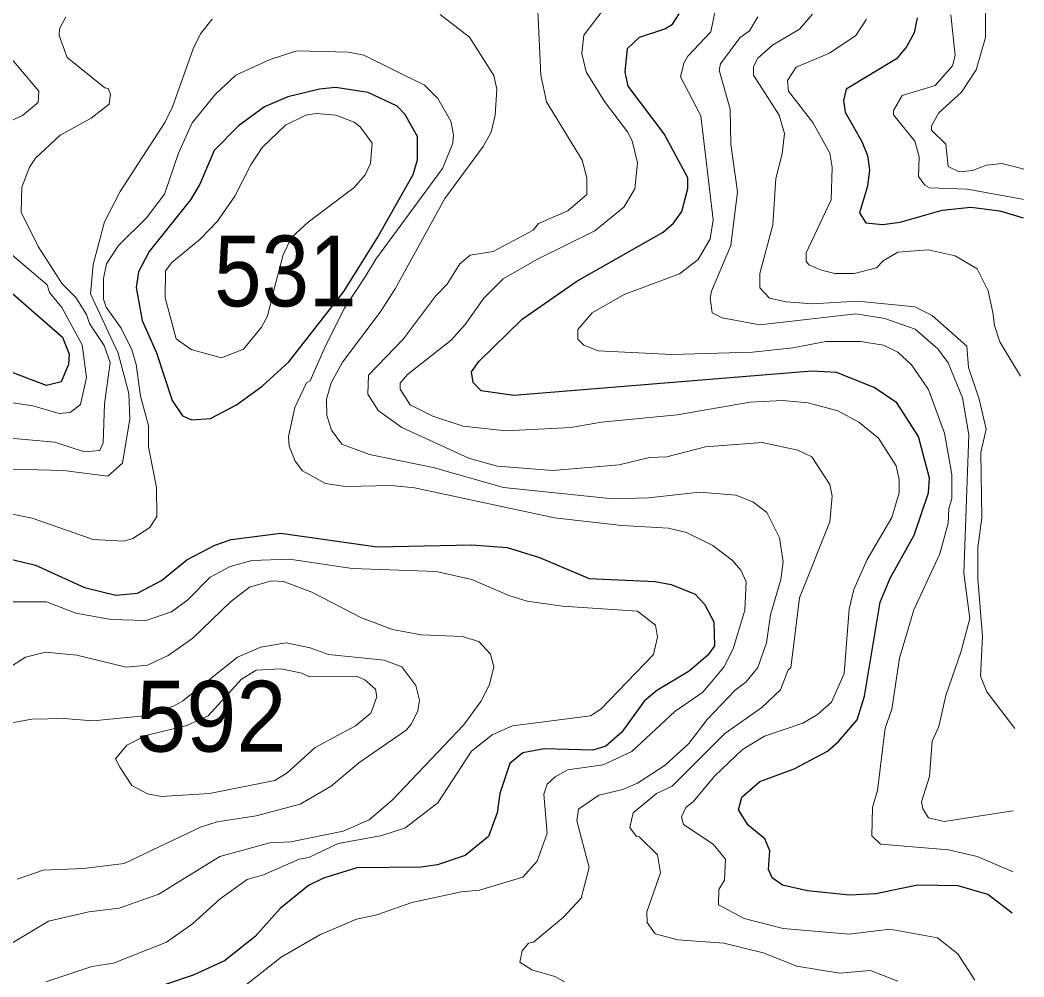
# Model space of a CAD drawing. Extents: x 673.3 to 698.5, y 6984.3 to 7012.3.
# Drawn here: x 696.93 to 698.064, y 6986.015 to 6987.096 of the extents above; entities that cross this region are included whole.
import ezdxf

# ---------------------------------------------------------------- set-up
doc = ezdxf.new("R2010")
doc.units = 0
doc.header["$LTSCALE"] = 0.032
doc.layers.add('1', color=7, linetype='Continuous', lineweight=25)
doc.layers.add('2', color=7, linetype='Continuous', lineweight=13)
doc.layers.add('21', color=7, linetype='Continuous')

msp = doc.modelspace()

# ---------------------------------------------------------------- linework, layer by layer
at = {"layer": '1'}
for points in [[(698.0509, 6986.0873), (698.0235, 6986.1082), (697.9901, 6986.118), (697.9442, 6986.1188), (697.897, 6986.109), (697.8672, 6986.1075), (697.82, 6986.1123), (697.7917, 6986.1188), (697.78, 6986.127), (697.7758, 6986.1366), (697.7775, 6986.1576), (697.7717, 6986.1711), (697.753, 6986.1866), (697.7418, 6986.2038), (697.7458, 6986.2181), (697.7662, 6986.2357), (697.8047, 6986.2501), (697.8425, 6986.2701), (697.855, 6986.2809), (697.876, 6986.3054), (697.8843, 6986.3324), (697.9018, 6986.4384), (697.9134, 6986.4655), (697.9404, 6986.5142), (697.9567, 6986.5618), (697.9575, 6986.5784), (697.9453, 6986.6253), (697.9208, 6986.6635), (697.8953, 6986.6809), (697.8525, 6986.6978), (697.8247, 6986.6994), (697.4881, 6986.6718), (697.4514, 6986.6771), (697.4421, 6986.6865), (697.4405, 6986.6983), (697.4487, 6986.7103), (697.4974, 6986.7578), (697.5595, 6986.8009), (697.6568, 6986.8563), (697.6684, 6986.8663), (697.6781, 6986.8795), (697.6847, 6986.9056), (697.6846, 6986.9177), (697.658, 6986.9672), (697.6173, 6987.0209), (697.6139, 6987.0367), (697.6166, 6987.0637), (697.63, 6987.0764), (697.6587, 6987.0857), (697.6673, 6987.091), (697.6749, 6987.1029)], [(697.9436, 6987.0984), (697.9403, 6987.0814), (697.9316, 6987.0654), (697.9205, 6987.0518), (697.8636, 6987.0176), (697.8606, 6987.0049), (697.8623, 6986.9916), (697.8813, 6986.9586), (697.8876, 6986.9426), (697.8899, 6986.9266), (697.8878, 6986.9082), (697.8787, 6986.8779), (697.8857, 6986.8669), (697.9047, 6986.8648), (697.9246, 6986.8675), (697.9719, 6986.881), (698.0045, 6986.8843)], [(698.0045, 6986.8843), (698.037, 6986.8803), (698.0561, 6986.8746), (698.0635, 6986.8724)], [(696.9222, 6986.7865), (696.9785, 6986.7377), (696.986, 6986.7183), (696.9851, 6986.7068), (696.9768, 6986.6873), (696.9602, 6986.6832), (696.9044, 6986.7041)], [(696.9105, 6986.4893), (696.948, 6986.4802), (697.0034, 6986.4551), (697.0386, 6986.4462), (697.0631, 6986.4486), (697.0903, 6986.4629), (697.119, 6986.4863), (697.1504, 6986.5027), (697.169, 6986.5092), (697.2249, 6986.5162), (697.334, 6986.5007), (697.4408, 6986.5033), (697.4806, 6986.5001), (697.5171, 6986.4888), (697.5732, 6986.465), (697.6478, 6986.4617), (697.6657, 6986.4585), (697.693, 6986.4476), (697.7034, 6986.4363), (697.7141, 6986.4161), (697.7149, 6986.3889), (697.7073, 6986.3784), (697.6861, 6986.3605), (697.6497, 6986.3386), (697.6353, 6986.3266), (697.61, 6986.2917), (697.5919, 6986.2757), (697.5773, 6986.2711), (697.5226, 6986.2727), (697.4985, 6986.2682), (697.4836, 6986.2562), (697.4723, 6986.2222), (697.4693, 6986.2004), (697.4594, 6986.1739), (697.4332, 6986.1524), (697.4018, 6986.1416), (697.3834, 6986.1392), (697.3109, 6986.1383), (697.2731, 6986.1268), (697.2562, 6986.1183), (697.2244, 6986.0925), (697.1959, 6986.0608), (697.1614, 6986.0335), (697.1259, 6986.0173), (696.9799, 6985.9679)]]:
    msp.add_lwpolyline(points, dxfattribs=at)
msp.add_lwpolyline([(697.3652, 6986.9895), (697.3565, 6986.9985), (697.3236, 6987.0139), (697.2868, 6987.0195), (697.2686, 6987.0178), (697.233, 6987.009), (697.2064, 6986.9978), (697.1771, 6986.9761), (697.1497, 6986.9486), (697.1334, 6986.9104), (697.123, 6986.8927), (697.0762, 6986.8343), (697.0643, 6986.8113), (697.0618, 6986.7939), (697.0685, 6986.7566), (697.0844, 6986.7201), (697.1023, 6986.6663), (697.1141, 6986.6488), (697.124, 6986.6442), (697.1454, 6986.6457), (697.1749, 6986.6611), (697.2039, 6986.6823), (697.234, 6986.7098), (697.296, 6986.7893), (697.334, 6986.8495), (697.3743, 6986.9215), (697.3793, 6986.938), (697.3794, 6986.9643)], close=True, dxfattribs=at)
at = {"layer": '2'}
for points in [[(698.0643, 6986.9275), (698.0574, 6986.9293), (698.0392, 6986.9339), (698.0222, 6986.9318), (698.0061, 6986.9257), (697.9911, 6986.9245), (697.9786, 6986.9305), (697.9761, 6986.9557), (697.96, 6986.9715), (697.96, 6986.9763), (697.9682, 6986.9909), (697.9937, 6987.0142), (698.0103, 6987.0396), (698.021, 6987.0759), (698.0211, 6987.1471)], [(697.3681, 6986.6955), (697.4173, 6986.7341), (697.4332, 6986.7518), (697.4542, 6986.7817), (697.476, 6986.8034), (697.5143, 6986.8255), (697.5796, 6986.8576), (697.6124, 6986.8846), (697.6249, 6986.905), (697.6278, 6986.9344), (697.622, 6986.9592), (697.6167, 6986.9696), (697.5907, 6987.0038), (697.57, 6987.0372), (697.5651, 6987.0579), (697.5674, 6987.0785), (697.6037, 6987.1267)], [(697.7189, 6987.1231), (697.7108, 6987.0826), (697.6846, 6987.0551), (697.6801, 6987.0469), (697.6766, 6987.0316), (697.6992, 6986.9875), (697.7132, 6986.8702), (697.7101, 6986.8486), (697.6964, 6986.8252), (697.6754, 6986.8093), (697.6128, 6986.786), (697.5765, 6986.7652), (697.5605, 6986.7463), (697.5606, 6986.7352), (697.5671, 6986.7285), (697.5833, 6986.7223), (697.6666, 6986.7181), (697.7578, 6986.7207), (697.8034, 6986.7255), (697.8406, 6986.7329), (697.8799, 6986.7328), (697.9057, 6986.7286), (697.9217, 6986.7206), (697.9375, 6986.7064), (697.9566, 6986.6785), (697.9745, 6986.6292), (697.9828, 6986.5824), (697.9829, 6986.5553), (697.9795, 6986.5437), (697.9787, 6986.5277), (697.9693, 6986.4928), (697.9401, 6986.4296), (697.9238, 6986.3751), (697.9151, 6986.3176), (697.9077, 6986.2961), (697.8988, 6986.2257), (697.8931, 6986.2065), (697.8924, 6986.1744), (697.9022, 6986.165), (697.979, 6986.1586), (698.0116, 6986.1513), (698.0513, 6986.1343), (698.0516, 6986.1342)], [(697.5144, 6987.1227), (697.5186, 6987.0335), (697.525, 6987.0035), (697.5652, 6986.9375), (697.5706, 6986.9175), (697.5707, 6986.8987), (697.549, 6986.8804), (697.516, 6986.8661), (697.5099, 6986.8585), (697.465, 6986.8344), (697.4388, 6986.8301), (697.427, 6986.8204)], [(697.6113, 6986.2268), (697.628, 6986.2341), (697.6591, 6986.2544), (697.6857, 6986.2787), (697.7065, 6986.3059), (697.738, 6986.3391), (697.7502, 6986.3481), (697.7637, 6986.3647), (697.7734, 6986.3925), (697.7781, 6986.4241), (697.7897, 6986.4641), (697.7922, 6986.4839), (697.7882, 6986.5111), (697.7738, 6986.5396), (697.7583, 6986.5515), (697.7391, 6986.5594), (697.6979, 6986.5626), (697.6402, 6986.5562), (697.5999, 6986.5552), (697.4764, 6986.5677), (697.397, 6986.5904), (697.325, 6986.6051), (697.2938, 6986.6167), (697.2821, 6986.6325), (697.2768, 6986.6492), (697.2767, 6986.6675), (697.2817, 6986.6859), (697.2947, 6986.7094), (697.3373, 6986.7659), (697.3543, 6986.7923), (697.4102, 6986.8941), (697.4536, 6986.953), (697.4624, 6986.9693), (697.4672, 6986.9883), (697.469, 6987.0177), (697.4655, 6987.033), (697.4381, 6987.0763), (697.4051, 6987.1019)], [(697.8255, 6987.1022), (697.811, 6987.0856), (697.7805, 6987.0674), (697.7638, 6987.0528), (697.7589, 6987.0431), (697.7589, 6987.0334), (697.788, 6986.9885), (697.7939, 6986.9678), (697.7913, 6986.9446), (697.784, 6986.9167), (697.7808, 6986.8646), (697.7662, 6986.8097), (697.7662, 6986.7932), (697.7769, 6986.7818), (697.7956, 6986.7775), (697.8252, 6986.7751), (697.8767, 6986.7784), (697.9409, 6986.772), (697.9608, 6986.7621), (697.9997, 6986.7275), (698.0016, 6986.7033), (698.0138, 6986.6675), (698.0218, 6986.6338), (698.0157, 6986.6074), (698.0169, 6986.5336), (698.0121, 6986.5002), (698.0121, 6986.4651), (698.0177, 6986.3995), (698.0154, 6986.3547), (698.0223, 6986.3371), (698.048, 6986.3037), (698.0542, 6986.2956)], [(697.9816, 6987.1015), (697.9868, 6987.0557), (697.9835, 6987.0442), (697.964, 6987.022), (697.9268, 6987.0106), (697.917, 6986.9937), (697.9169, 6986.9886), (697.9412, 6986.9591), (697.9461, 6986.9414), (697.9453, 6986.9189), (697.9522, 6986.9091), (697.9577, 6986.9061), (698.0002, 6986.9046), (698.0627, 6986.8933), (698.0638, 6986.8931)], [(696.8515, 6986.6296), (696.9699, 6986.6189), (697.0032, 6986.6083), (697.0205, 6986.6097), (697.0242, 6986.6184), (697.0258, 6986.6625), (697.0322, 6986.7091), (697.0254, 6986.7281), (697.009, 6986.7531), (697.0056, 6986.7633), (696.9933, 6986.7825), (696.978, 6986.7978), (696.9508, 6986.8399), (696.9318, 6986.8788), (696.9323, 6986.9071), (696.941, 6986.9296), (696.9478, 6986.9399), (696.9757, 6986.9659), (697.0109, 6986.9849), (697.031, 6987.0009), (697.0325, 6987.0122), (697.0299, 6987.0186), (697.0262, 6987.0191), (696.9838, 6987.0533), (696.9745, 6987.0784), (696.9752, 6987.0857), (696.982, 6987.0993)], [(697.1473, 6987.0968), (697.1343, 6987.08), (697.1259, 6987.0633), (697.1028, 6986.9977), (697.0941, 6986.9802), (697.0437, 6986.9023), (697.0257, 6986.8677), (697.013, 6986.8197), (697.01, 6986.7865), (697.0414, 6986.7196), (697.0535, 6986.6739), (697.0545, 6986.6454), (697.0463, 6986.5954), (697.0295, 6986.5806), (696.9796, 6986.5869), (696.9226, 6986.5887)], [(698.0527, 6986.2029), (698.047, 6986.202), (697.9742, 6986.1908), (697.9565, 6986.1949), (697.9503, 6986.2049), (697.9486, 6986.2129), (697.9576, 6986.2415), (697.9608, 6986.2814), (697.9681, 6986.298), (697.976, 6986.3329), (697.9934, 6986.3829), (698.0031, 6986.4201), (697.9966, 6986.471), (698.002, 6986.6272), (697.9949, 6986.6693), (697.9786, 6986.7087), (697.9672, 6986.7246), (697.9415, 6986.7465), (697.9073, 6986.7588), (697.8743, 6986.7638), (697.7661, 6986.7516), (697.7236, 6986.7596), (697.7123, 6986.7652), (697.71, 6986.7815), (697.7113, 6986.7896), (697.7333, 6986.841), (697.7409, 6986.9016), (697.7331, 6986.9554), (697.7327, 6986.9951), (697.7202, 6987.039), (697.7217, 6987.0462), (697.7436, 6987.0758), (697.7543, 6987.0834), (697.7637, 6987.0993)], [(698.0606, 6986.6936), (698.0372, 6986.7323), (698.0309, 6986.7507), (698.0291, 6986.7654), (698.0238, 6986.7899), (698.0114, 6986.8147), (697.9866, 6986.8294), (697.9562, 6986.8362), (697.9218, 6986.8338), (697.9053, 6986.8239), (697.8978, 6986.8161), (697.8727, 6986.8096), (697.8509, 6986.8094), (697.8357, 6986.8134), (697.8215, 6986.8194), (697.8183, 6986.8235), (697.8185, 6986.8327), (697.8467, 6986.8927), (697.8476, 6986.9297), (697.8449, 6986.9455), (697.8257, 6986.9802), (697.7983, 6987.0156), (697.7972, 6987.0276), (697.8071, 6987.0424), (697.8446, 6987.0583), (697.8744, 6987.0782), (697.8865, 6987.0969)], [(696.8984, 6987.0784), (696.9516, 6987.0153), (696.9509, 6987.0027), (696.9333, 6986.9879), (696.9161, 6986.9799)], [(696.9198, 6986.5382), (696.9441, 6986.5334), (697.0131, 6986.5092), (697.0478, 6986.5071), (697.058, 6986.5103), (697.0772, 6986.5228), (697.085, 6986.5352), (697.0846, 6986.5677), (697.0756, 6986.6137), (697.0756, 6986.6378), (697.0666, 6986.671), (697.0617, 6986.7068), (697.0567, 6986.7233), (697.0445, 6986.7478), (697.0276, 6986.7714), (697.0246, 6986.7804), (697.0247, 6986.804), (697.0282, 6986.8204), (697.0415, 6986.8411), (697.0734, 6986.8724), (697.0938, 6986.8991), (697.1093, 6986.9456), (697.1247, 6986.9796), (697.1514, 6987.0121), (697.1743, 6987.0335), (697.2128, 6987.0513), (697.2431, 6987.0609), (697.3014, 6987.0593), (697.3187, 6987.0562), (697.3873, 6987.0221), (697.4023, 6987.0071), (697.4169, 6986.9815), (697.42, 6986.9663), (697.4193, 6986.9566), (697.4077, 6986.9281), (697.3322, 6986.8259), (697.3201, 6986.8058), (697.2969, 6986.7703), (697.2764, 6986.7293), (697.258, 6986.6885), (697.254, 6986.6862), (697.241, 6986.6582), (697.2336, 6986.6256), (697.2346, 6986.6144), (697.2412, 6986.5977), (697.2496, 6986.5866), (697.2754, 6986.5723), (697.2982, 6986.5691), (697.3495, 6986.57), (697.3759, 6986.5676), (697.5341, 6986.5338), (697.61, 6986.525), (697.6627, 6986.5219), (697.6833, 6986.5172), (697.713, 6986.5025), (697.735, 6986.4854), (697.7445, 6986.4744), (697.7506, 6986.4613), (697.7489, 6986.4293), (697.7359, 6986.3857), (697.7255, 6986.3648), (697.7015, 6986.3366), (697.6702, 6986.315), (697.6215, 6986.2699), (697.5892, 6986.2547), (697.5488, 6986.249), (697.5349, 6986.2412), (697.526, 6986.2327), (697.5219, 6986.2215), (697.5259, 6986.1777), (697.5146, 6986.1458), (697.4984, 6986.128), (697.4493, 6986.113), (697.4292, 6986.1113), (697.3728, 6986.0992), (697.3334, 6986.0853), (697.3103, 6986.0803), (697.2692, 6986.0628), (697.2252, 6986.0374), (697.1415, 6985.9711)], [(696.9182, 6986.8332), (696.9611, 6986.7968), (696.9636, 6986.7881), (696.9778, 6986.7711), (697.0005, 6986.7289), (697.0054, 6986.6919), (696.9987, 6986.6616), (696.9871, 6986.6524), (696.9748, 6986.6514), (696.945, 6986.6602), (696.8669, 6986.6717)], [(697.427, 6986.8204), (697.413, 6986.7976), (697.3998, 6986.784), (697.3634, 6986.7356), (697.3242, 6986.6947), (697.3231, 6986.6733), (697.3349, 6986.655), (697.3617, 6986.6358), (697.4382, 6986.6007), (697.4699, 6986.592), (697.5322, 6986.5871), (697.607, 6986.5935), (697.6415, 6986.6017), (697.6609, 6986.6025), (697.7045, 6986.6139), (697.7686, 6986.6188), (697.8091, 6986.6099), (697.8248, 6986.6025), (697.8451, 6986.5714), (697.8476, 6986.5581), (697.8451, 6986.529), (697.811, 6986.4432), (697.8011, 6986.3642), (697.7979, 6986.362), (697.7892, 6986.3393), (697.7681, 6986.3193), (697.7265, 6986.29), (697.6669, 6986.2306), (697.6492, 6986.2223), (697.6231, 6986.2004), (697.6191, 6986.1841), (697.6268, 6986.1737), (697.6299, 6986.1733), (697.6506, 6986.1532), (697.6537, 6986.1329), (697.6383, 6986.0888), (697.6386, 6986.0766), (697.6479, 6986.0637), (697.6734, 6986.057), (697.7252, 6986.0535), (697.7699, 6986.0423), (697.8077, 6986.0272), (697.8559, 6986.0195), (697.8912, 6986.0226), (697.9217, 6986.0104)], [(698.009, 6986.0114), (697.9895, 6986.0412), (697.9667, 6986.0594), (697.9127, 6986.0691), (697.8669, 6986.0635), (697.7924, 6986.07), (697.7485, 6986.081), (697.7193, 6986.0965), (697.7198, 6986.1141), (697.7262, 6986.1246), (697.7272, 6986.1482), (697.7132, 6986.1652), (697.6798, 6986.1873), (697.6775, 6986.196), (697.6823, 6986.2067), (697.6909, 6986.2129), (697.7148, 6986.2418), (697.7466, 6986.2719), (697.7713, 6986.287), (697.8147, 6986.3019), (697.831, 6986.3114), (697.847, 6986.3254), (697.8613, 6986.3577), (697.867, 6986.4305), (697.8723, 6986.4526), (697.8871, 6986.4864), (697.9151, 6986.5339), (697.9233, 6986.5618), (697.9233, 6986.577), (697.92, 6986.5924), (697.8999, 6986.6235), (697.878, 6986.6415), (697.854, 6986.6544), (697.8207, 6986.6636), (697.7917, 6986.666), (697.7552, 6986.6644), (697.6728, 6986.6498), (697.5872, 6986.6416), (697.5526, 6986.6358), (697.4797, 6986.6319), (697.4308, 6986.6373), (697.3966, 6986.6484), (697.3712, 6986.6612), (697.3599, 6986.6791), (697.3599, 6986.6856), (697.3681, 6986.6955)], [(696.9597, 6986.0095), (697.0115, 6986.0268), (697.0359, 6986.0309), (697.0957, 6986.0543), (697.1253, 6986.075), (697.1564, 6986.1035), (697.1869, 6986.1252), (697.2056, 6986.1304), (697.2458, 6986.1481), (697.2565, 6986.1501), (697.2897, 6986.166), (697.3377, 6986.1747), (697.3652, 6986.183), (697.4023, 6986.2119), (697.4403, 6986.2701), (697.4638, 6986.2884), (697.4866, 6986.2987), (697.5748, 6986.3102), (697.5863, 6986.3177), (697.646, 6986.3793), (697.6505, 6986.3987), (697.6481, 6986.4123), (697.6277, 6986.4283), (697.5432, 6986.434), (697.5034, 6986.4396), (697.4825, 6986.4459), (697.4409, 6986.4641), (697.4005, 6986.473), (697.3054, 6986.4763), (697.2348, 6986.4869), (697.1923, 6986.4853), (697.1676, 6986.4787), (697.1452, 6986.4667), (697.12, 6986.4409), (697.1014, 6986.4273), (697.0725, 6986.4178), (697.0334, 6986.4188), (696.9933, 6986.4259), (696.9604, 6986.4388), (696.9207, 6986.4387)], [(696.9056, 6986.3567), (696.9366, 6986.3761), (696.9591, 6986.3818), (696.9947, 6986.3786), (697.0502, 6986.3649), (697.0745, 6986.3671), (697.0977, 6986.3783), (697.1255, 6986.3978), (697.1681, 6986.4386), (697.1895, 6986.4553), (697.2143, 6986.4624), (697.2281, 6986.4616), (697.2599, 6986.4498), (697.3161, 6986.4208), (697.3511, 6986.4075), (697.3836, 6986.4014), (697.4297, 6986.3997), (697.4485, 6986.394), (697.4618, 6986.3798), (697.4657, 6986.3654), (697.4608, 6986.3455), (697.4509, 6986.3262), (697.4312, 6986.2994), (697.3506, 6986.2147), (697.3247, 6986.1924), (697.2956, 6986.1799), (697.2363, 6986.1677), (697.2126, 6986.1667), (697.1562, 6986.1513), (697.0872, 6986.1088), (697.0425, 6986.0928), (697.0083, 6986.0887), (696.9626, 6986.0781), (696.904, 6986.0432)], [(696.9271, 6986.1256), (696.9564, 6986.1359), (697.002, 6986.1376), (697.048, 6986.1434), (697.1344, 6986.1843), (697.1532, 6986.1905), (697.1972, 6986.197), (697.2469, 6986.2102), (697.2819, 6986.2305), (697.313, 6986.2568), (697.3664, 6986.294), (697.3726, 6986.301), (697.3797, 6986.3157), (697.3817, 6986.3279), (697.3773, 6986.3441), (697.3618, 6986.3655), (697.3418, 6986.3728), (697.2787, 6986.3794), (697.2582, 6986.3868), (697.2311, 6986.3924), (697.2024, 6986.3877), (697.176, 6986.3763), (697.1145, 6986.327), (697.1038, 6986.321), (697.0706, 6986.3099), (697.0125, 6986.3044), (696.9799, 6986.307), (696.9438, 6986.3061), (696.9065, 6986.2994)], [(697.5454, 6986.0096), (697.5346, 6986.0158), (697.5086, 6986.0233), (697.495, 6986.032), (697.4975, 6986.0447), (697.5047, 6986.0535), (697.5104, 6986.0546), (697.5443, 6986.0825), (697.5641, 6986.1043), (697.5731, 6986.1386), (697.5593, 6986.1915), (697.5614, 6986.2048), (697.5843, 6986.2204), (697.6113, 6986.2268)]]:
    msp.add_lwpolyline(points, dxfattribs=at)
for points in [[(697.1912, 6986.9324), (697.2041, 6986.9518), (697.2301, 6986.9772), (697.2533, 6986.9883), (697.2651, 6986.9901), (697.2872, 6986.9885), (697.3078, 6986.9806), (697.3145, 6986.9753), (697.328, 6986.9567), (697.3264, 6986.9339), (697.3204, 6986.9209), (697.3078, 6986.9066), (697.2559, 6986.8676), (697.2369, 6986.8501), (697.2275, 6986.8305), (697.218, 6986.7938), (697.2101, 6986.7614), (697.2033, 6986.7489), (697.183, 6986.7239), (697.158, 6986.7142), (697.1237, 6986.7238), (697.1068, 6986.7359), (697.0942, 6986.782), (697.0949, 6986.8126), (697.1019, 6986.8218), (697.1339, 6986.8482), (697.1535, 6986.8686), (697.1729, 6986.8967)], [(697.3095, 6986.2988), (697.3266, 6986.313), (697.3336, 6986.3315), (697.3321, 6986.3402), (697.3199, 6986.3506), (697.31, 6986.3548), (697.2573, 6986.3542), (697.2487, 6986.3583), (697.2252, 6986.363), (697.1972, 6986.3615), (697.1804, 6986.3514), (697.1429, 6986.31), (697.1189, 6986.2991), (697.0725, 6986.2877), (697.051, 6986.2768), (697.0384, 6986.2613), (697.0433, 6986.252), (697.0569, 6986.2313), (697.0744, 6986.2218), (697.0897, 6986.2191), (697.1446, 6986.2222), (697.2182, 6986.2371), (697.2322, 6986.2458), (697.2638, 6986.2744)]]:
    msp.add_lwpolyline(points, close=True, dxfattribs=at)

# ---------------------------------------------------------------- texts
at = {"layer": '21'}
for s, width, p in [('531', 0.9, (697.1497, 6986.7724)), ('592', 0.95, (697.0617, 6986.2696))]:
    msp.add_text(s, height=0.08, dxfattribs=dict(at, width=width)).set_placement(p)

doc.saveas('drawing.dxf')
